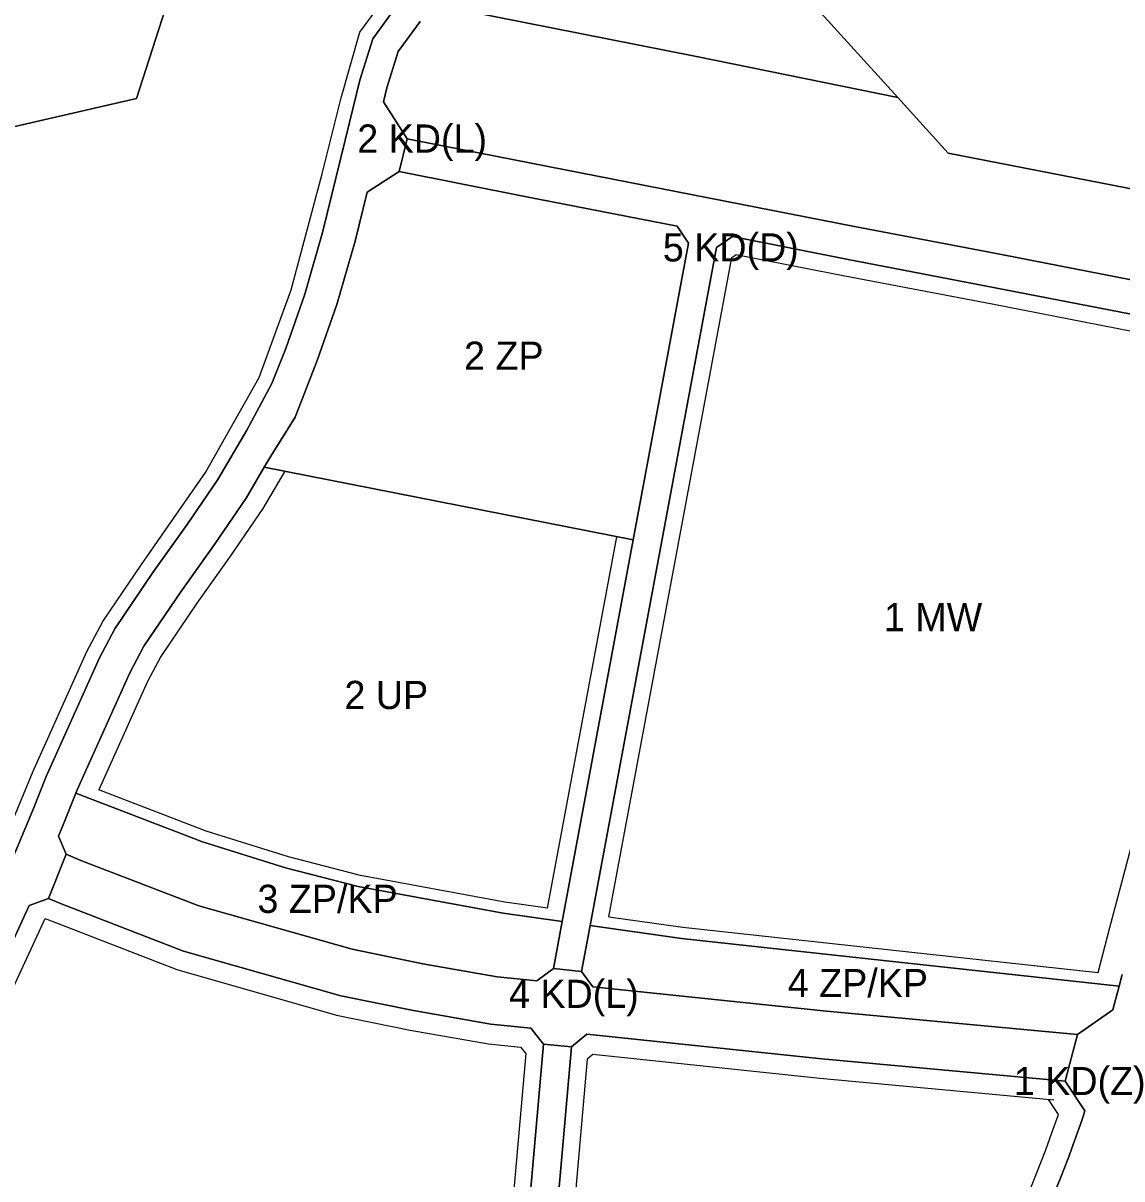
# Model space of a CAD drawing. Extents: x 7424258 to 7426021, y 5551671 to 5553193.
# Drawn here: x 7425010.8 to 7425401.1, y 5552263 to 5552673.5 of the extents above; entities that cross this region are included whole.
import ezdxf

# ---------------------------------------------------------------- set-up
doc = ezdxf.new("R2010")
doc.units = 0
for name, color, linetype in [('linie_rozgraniczajace', 7, 'Continuous'), ('linie_zabudowy_nieprzekraczalne', 7, 'Continuous'), ('oznaczenia_przeznaczen', 7, 'Continuous')]:
    doc.layers.add(name, color=color, linetype=linetype)

msp = doc.modelspace()

# ---------------------------------------------------------------- linework, layer by layer
at = {"layer": 'linie_rozgraniczajace'}
for points in [[(7425157.19, 5552680.03), (7425160.97, 5552684.22), (7425170.67, 5552693.25), (7425187.71, 5552708.55), (7425210.71, 5552727.51), (7425217.99, 5552734.05), (7425224.54, 5552739.63), (7425232.89, 5552746.19), (7425235.4, 5552745.61), (7425242.15, 5552744.04), (7425246.59, 5552743.19), (7425240.08, 5552737.14), (7425251.22, 5552724.52), (7425321.43, 5552647.09), (7425301.71, 5552651.12), (7425250.04, 5552661.6)], [(7425144.37, 5552620.75), (7425147.23, 5552632.41), (7425191.3, 5552623.7), (7425306.08, 5552601.31), (7425358.36, 5552591.28), (7425424.98, 5552578.29), (7425465.64, 5552570.34), (7425459.57, 5552559.28), (7425422.69, 5552566.52), (7425356.08, 5552579.5), (7425303.8, 5552589.54), (7425262.75, 5552597.67), (7425257.06, 5552593.76), (7425212.18, 5552352.94), (7425209.14, 5552336.67), (7425199.16, 5552337.71), (7425202.26, 5552354.34), (7425227.54, 5552489.91), (7425247.19, 5552595.37), (7425243.07, 5552601.38), (7425188.99, 5552611.93)], [(7425096.46, 5552515.81), (7425098.75, 5552519.71), (7425107.41, 5552533.57), (7425115.32, 5552553.65), (7425122.28, 5552573.56), (7425128.74, 5552596.06), (7425133, 5552613.41), (7425144.37, 5552620.75), (7425188.99, 5552611.93), (7425243.07, 5552601.38), (7425247.19, 5552595.37), (7425227.54, 5552489.91)], [(7425029.59, 5552399.95), (7425030.08, 5552401.17), (7425048.72, 5552442.76), (7425053.72, 5552452.15), (7425066.79, 5552471.48), (7425079.01, 5552488.6), (7425090, 5552504.8), (7425096.46, 5552515.81), (7425227.54, 5552489.91), (7425202.26, 5552354.34), (7425181.29, 5552357.3), (7425129.77, 5552366.83), (7425103.99, 5552373.46), (7425074.56, 5552382.67)], [(7425023.39, 5552384.75), (7425025.35, 5552389.37), (7425029.59, 5552399.95), (7425074.56, 5552382.67), (7425103.99, 5552373.46), (7425129.77, 5552366.83), (7425181.29, 5552357.3), (7425202.26, 5552354.34), (7425199.16, 5552337.71), (7425193.28, 5552333.32), (7425179.25, 5552334.78), (7425152.84, 5552339.41), (7425127.66, 5552344.52), (7425073.25, 5552360.01), (7425031.34, 5552376.1), (7425026.11, 5552378.35)], [(7425019.81, 5552362.55), (7425026.11, 5552378.35), (7425031.34, 5552376.1), (7425073.25, 5552360.01), (7425127.66, 5552344.52), (7425152.84, 5552339.41), (7425179.25, 5552334.78), (7425193.28, 5552333.32), (7425199.16, 5552337.71), (7425209.14, 5552336.67), (7425213.2, 5552331.24), (7425296.12, 5552322.57), (7425385.35, 5552314.3), (7425380.86, 5552297.64), (7425294.46, 5552305.65), (7425211.02, 5552314.38), (7425205.62, 5552309.91), (7425195.65, 5552310.79), (7425191.14, 5552316.45), (7425176.9, 5552317.94), (7425149.52, 5552322.73), (7425123.64, 5552327.99), (7425067.84, 5552343.87), (7425024.68, 5552360.58)], [(7425209.14, 5552336.67), (7425212.18, 5552352.94), (7425244.64, 5552348.36), (7425400.09, 5552331.38), (7425397.9, 5552323.04), (7425385.35, 5552314.3), (7425296.12, 5552322.57), (7425213.2, 5552331.24)], [(7425167.65, 5552081.05), (7425181.78, 5552153.52), (7425195.65, 5552310.79), (7425205.62, 5552309.91), (7425191.71, 5552152.38), (7425178.53, 5552084.62)]]:
    msp.add_lwpolyline(points, close=True, dxfattribs=at)
for points in [[(7425005.09, 5552735), (7425022.74, 5552738.06), (7425041.97, 5552740.23), (7425053.23, 5552741.21), (7425069.03, 5552742.21), (7425077.14, 5552727.76), (7425051.06, 5552646.66), (7424995.42, 5552633.88)], [(7424995.42, 5552633.88), (7425051.06, 5552646.66), (7425077.14, 5552727.76)], [(7425516.29, 5552674.09), (7425501.98, 5552660.41), (7425488.46, 5552648.19), (7425465.82, 5552636.34), (7425440.5, 5552624.42), (7425436.43, 5552625.15), (7425411.75, 5552613.27), (7425339.38, 5552627.28), (7425321.43, 5552647.09), (7425251.22, 5552724.52)], [(7425002.08, 5552365.14), (7425014.25, 5552393.94), (7425019.03, 5552405.85), (7425037.94, 5552448.05), (7425043.43, 5552458.35), (7425056.93, 5552478.32), (7425069.15, 5552495.44), (7425079.95, 5552511.39), (7425090.31, 5552528.92), (7425099.21, 5552545.5), (7425104.09, 5552557.9), (7425110.84, 5552577.19), (7425117.13, 5552599.14), (7425126.73, 5552638.2), (7425130.42, 5552653.24), (7425134.98, 5552667.96), (7425144.03, 5552680.38)], [(7425144.03, 5552680.38), (7425134.98, 5552667.96), (7425130.42, 5552653.24), (7425126.73, 5552638.2), (7425117.13, 5552599.14), (7425110.84, 5552577.19), (7425104.09, 5552557.9), (7425099.21, 5552545.5), (7425090.31, 5552528.92), (7425079.95, 5552511.39), (7425069.15, 5552495.44), (7425056.93, 5552478.32), (7425043.43, 5552458.35), (7425037.94, 5552448.05), (7425019.03, 5552405.85), (7425014.25, 5552393.94), (7425002.08, 5552365.14)], [(7425612.91, 5552678.24), (7425600.34, 5552673.3), (7425588.67, 5552668.46), (7425576.97, 5552662.59), (7425567.32, 5552657.74), (7425552.82, 5552648.5), (7425542.61, 5552641.71), (7425530.42, 5552632.09), (7425512.79, 5552616.41), (7425499.46, 5552601.97), (7425487.18, 5552586.84), (7425480.2, 5552577.11), (7425465.64, 5552570.34), (7425424.98, 5552578.29), (7425358.36, 5552591.28), (7425306.08, 5552601.31), (7425191.3, 5552623.7), (7425147.23, 5552632.41), (7425138.81, 5552645.48), (7425140.06, 5552650.56), (7425144.04, 5552663.41), (7425151.8, 5552674.07)], [(7425157.19, 5552680.03), (7425250.04, 5552661.6), (7425301.71, 5552651.12), (7425321.43, 5552647.09), (7425339.38, 5552627.28), (7425411.75, 5552613.27), (7425436.43, 5552625.15), (7425440.5, 5552624.42), (7425465.82, 5552636.34), (7425488.46, 5552648.19), (7425501.98, 5552660.41), (7425516.29, 5552674.09)], [(7425151.8, 5552674.07), (7425144.04, 5552663.41), (7425140.06, 5552650.56), (7425138.81, 5552645.48), (7425147.23, 5552632.41), (7425144.37, 5552620.75), (7425133, 5552613.41), (7425128.74, 5552596.06), (7425122.28, 5552573.56), (7425115.32, 5552553.65), (7425107.41, 5552533.57), (7425098.75, 5552519.71), (7425096.46, 5552515.81), (7425090, 5552504.8), (7425079.01, 5552488.6), (7425066.79, 5552471.48), (7425053.72, 5552452.15), (7425048.72, 5552442.76), (7425030.08, 5552401.17), (7425029.59, 5552399.95), (7425025.35, 5552389.37), (7425023.39, 5552384.75), (7425026.11, 5552378.35), (7425019.81, 5552362.55), (7425012.96, 5552360.1), (7424997.27, 5552325.91)], [(7425401.21, 5552335.58), (7425400.09, 5552331.38), (7425244.64, 5552348.36), (7425212.18, 5552352.94), (7425257.06, 5552593.76), (7425262.75, 5552597.67), (7425303.8, 5552589.54), (7425356.08, 5552579.5), (7425422.69, 5552566.52)], [(7424997.27, 5552325.91), (7425012.96, 5552360.1), (7425019.81, 5552362.55), (7425024.68, 5552360.58), (7425067.84, 5552343.87), (7425123.64, 5552327.99), (7425149.52, 5552322.73), (7425176.9, 5552317.94), (7425191.14, 5552316.45), (7425195.65, 5552310.79), (7425181.78, 5552153.52), (7425167.65, 5552081.05), (7425156.08, 5552068.62), (7425148.38, 5552066.54), (7425124.54, 5552060.86), (7425088.94, 5552055.71), (7425056.14, 5552052.4), (7425032.48, 5552051.43), (7424996.02, 5552051.74)], [(7425376.51, 5552256.56), (7425379.37, 5552263.62), (7425381.98, 5552270.26), (7425384.18, 5552276.48), (7425386.8, 5552283.67), (7425387.94, 5552287.14), (7425380.86, 5552297.64), (7425385.35, 5552314.3), (7425397.9, 5552323.04), (7425400.09, 5552331.38), (7425401.21, 5552335.58)], [(7425191.71, 5552152.38), (7425205.62, 5552309.91), (7425211.02, 5552314.38), (7425294.46, 5552305.65), (7425380.86, 5552297.64), (7425387.94, 5552287.14), (7425386.8, 5552283.67), (7425384.18, 5552276.48), (7425381.98, 5552270.26), (7425379.37, 5552263.62), (7425376.51, 5552256.56)]]:
    msp.add_lwpolyline(points, dxfattribs=at)
at = {"layer": 'linie_zabudowy_nieprzekraczalne'}
for points in [[(7425003.55, 5552381.47), (7425014.43, 5552407.8), (7425033.44, 5552450.25), (7425039.15, 5552460.94), (7425052.83, 5552481.18), (7425075.64, 5552513.93), (7425094.67, 5552547.61), (7425106.07, 5552578.7), (7425117.09, 5552619.91), (7425123.73, 5552646.98), (7425130.45, 5552670.24), (7425140.15, 5552683.54), (7425145.19, 5552689.13), (7425160.55, 5552704.33), (7425178.18, 5552720.14), (7425208.62, 5552745.22)], [(7425218.86, 5552356.04), (7425262.5, 5552590.21)], [(7425262.5, 5552590.21), (7425263.93, 5552591.2)], [(7425452.42, 5552554.59), (7425421.53, 5552560.63), (7425354.94, 5552573.61), (7425302.66, 5552583.64), (7425263.93, 5552591.2)], [(7425392.58, 5552336.23), (7425396.8, 5552352.26), (7425401.12, 5552368.72), (7425404.9, 5552383.08), (7425411.57, 5552408.47), (7425419.93, 5552440.28), (7425423.74, 5552454.77), (7425425.42, 5552461.15), (7425430.68, 5552480.9), (7425435, 5552498.41), (7425439.37, 5552513.23), (7425441.92, 5552520.67), (7425444.67, 5552528.02), (7425445.35, 5552529.6), (7425448.62, 5552537.24), (7425452.46, 5552545.68), (7425454.68, 5552550.13)], [(7425103.73, 5552514.36), (7425095.91, 5552501.05), (7425084.75, 5552484.6), (7425072.54, 5552467.48), (7425059.73, 5552448.54), (7425055.01, 5552439.69), (7425037.73, 5552401.11)], [(7425197.05, 5552359.12), (7425221.65, 5552491.07)], [(7425197.05, 5552359.12), (7425181.93, 5552361.25), (7425130.63, 5552370.74), (7425105.09, 5552377.31), (7425075.87, 5552386.45), (7425037.73, 5552401.11)], [(7425218.86, 5552356.04), (7425245.13, 5552352.33), (7425392.58, 5552336.23)], [(7425003.72, 5552323.19), (7425018.64, 5552355.47), (7425018.64, 5552355.47), (7425065.41, 5552337.31), (7425122.17, 5552321.15), (7425148.25, 5552315.85), (7425176.1, 5552310.98), (7425187.49, 5552309.79), (7425189.34, 5552307.48), (7425175.83, 5552154.35), (7425162.98, 5552088.46), (7425162.92, 5552088.44), (7425151.52, 5552076.19), (7425146.25, 5552074.77), (7425122.95, 5552069.22), (7425087.91, 5552064.15), (7425055.54, 5552060.89), (7425032.35, 5552059.93), (7424996.07, 5552060.24)], [(7425376.93, 5552290.95), (7425293.8, 5552298.69), (7425213.21, 5552307.11), (7425213.21, 5552307.11), (7425211.2, 5552305.45), (7425197.65, 5552151.43), (7425185.63, 5552089.69), (7425188.03, 5552087.58)], [(7425188.03, 5552087.58), (7425210.25, 5552095.93), (7425226.02, 5552102.49), (7425244.84, 5552111.51), (7425259.84, 5552120.68), (7425269.53, 5552127.76), (7425282.47, 5552138.2), (7425292.44, 5552147.09), (7425301.47, 5552155.87), (7425312.51, 5552167.69), (7425319.72, 5552176.13), (7425330.43, 5552189.95), (7425337.44, 5552199.99), (7425347.97, 5552216.93), (7425354.1, 5552228.08), (7425360.21, 5552240.47), (7425365.08, 5552251.53), (7425368.67, 5552259.84), (7425374.02, 5552273.24), (7425376.18, 5552279.35), (7425378.55, 5552285.86), (7425375, 5552291.13), (7425375, 5552291.13)]]:
    msp.add_lwpolyline(points, dxfattribs=at)

# ---------------------------------------------------------------- texts
at = {"layer": 'oznaczenia_przeznaczen'}
for s, p in [('2 KD(L)', (7425129.51, 5552627.49)), ('5 KD(D)', (7425238.03, 5552588.84)), ('2 ZP', (7425167.43, 5552550.37)), ('1 MW', (7425316.56, 5552457.52)), ('2 UP', (7425124.95, 5552429.87)), ('3 ZP/KP', (7425094.06, 5552357.45)), ('4 ZP/KP', (7425282.4, 5552327.53)), ('4 KD(L)', (7425183.4, 5552323.7)), ('1 KD(Z)', (7425362.69, 5552292.72))]:
    msp.add_text(s, height=10, dxfattribs=at).set_placement(p)

doc.saveas('drawing.dxf')
